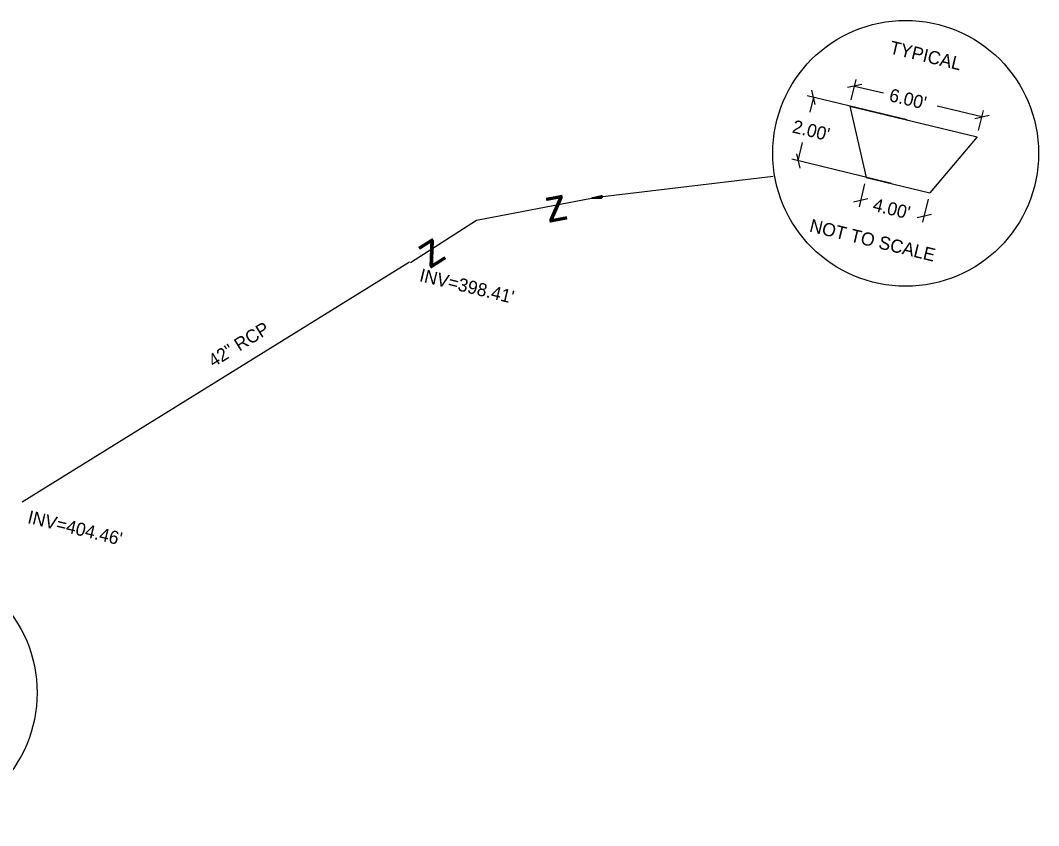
# Model space of a CAD drawing. Extents: x 1975859 to 1978323, y 778892 to 782836.
# Drawn here: x 1977755 to 1978066, y 779985 to 780231 of the extents above; entities that cross this region are included whole.
import ezdxf

# ---------------------------------------------------------------- set-up
doc = ezdxf.new("R2010")
doc.units = 0
for name, color, linetype in [('Exist Structure Minor Pipes RCP 42 Inch', 7, 'Continuous'), ('Exist Structure Minor Pipes RCP 42 Inch Invert', 7, 'Continuous'), ('Exist Structure Minor Pipes RCP 42 Inch Text', 7, 'Continuous'), ('Scratch_Level_8', 7, 'Continuous')]:
    doc.layers.add(name, color=color, linetype=linetype)

msp = doc.modelspace()

# ---------------------------------------------------------------- linework, layer by layer
at = {"layer": 'Exist Structure Minor Pipes RCP 42 Inch'}
msp.add_line((1977873.82, 780157.16), (1977755.54, 780083.84), dxfattribs=at)
at = {"layer": 'Scratch_Level_8'}
for p, q in [((1978008.8, 780206.78), (1978010.29, 780212.91)), ((1977997.74, 780205.34), (1977996.74, 780209.7)), ((1978012, 780211.46), (1978007.64, 780210.46)), ((1978009.82, 780210.96), (1978018.62, 780208.83)), ((1978025.82, 780200.59), (1977995.3, 780207.99)), ((1977997.24, 780207.52), (1977996.13, 780202.94)), ((1978008.33, 780204.83), (1978047.2, 780195.41)), ((1978008.33, 780204.83), (1978013.34, 780183.04)), ((1978048.69, 780201.53), (1978035.01, 780204.85)), ((1978047.68, 780197.35), (1978049.16, 780203.48)), ((1978046.51, 780201.03), (1978050.87, 780202.03)), ((1977992.53, 780188.09), (1977993.9, 780193.75)), ((1978047.2, 780195.41), (1978032.77, 780178.33)), ((1977992.03, 780190.27), (1977993.03, 780185.91)), ((1978021.11, 780181.15), (1977990.59, 780188.56)), ((1977984.93, 780183.31), (1977929.4, 780176.73)), ((1978012.86, 780181.1), (1978011.16, 780174.08)), ((1978013.34, 780183.04), (1978032.77, 780178.33)), ((1977932.38, 780177.08), (1977932.62, 780177.33)), ((1977932.38, 780177.08), (1977932.68, 780177.28)), ((1977932.38, 780177.08), (1977932.69, 780177.18)), ((1977932.68, 780176.9), (1977932.38, 780177.08)), ((1977932.38, 780177.08), (1977932.7, 780177.06)), ((1977932.38, 780177.08), (1977932.71, 780176.97)), ((1977932.66, 780177.38), (1977932.73, 780176.85)), ((1978013.81, 780176.52), (1978009.45, 780175.52)), ((1978032.3, 780176.38), (1978030.6, 780169.36)), ((1978028.89, 780170.81), (1978033.25, 780171.81))]:
    msp.add_line(p, q, dxfattribs=at)
for points in [[(1977874.1, 780157.02), (1977894.26, 780169.96), (1977929.4, 780176.73)], [(1977932.66, 780177.38), (1977932.42, 780177.45), (1977929.4, 780176.73), (1977932.51, 780176.74), (1977932.73, 780176.85)], [(1977932.62, 780176.8), (1977929.4, 780176.73), (1977932.54, 780177.42)], [(1977932.52, 780177.31), (1977929.4, 780176.73), (1977932.66, 780177.38), (1977932.62, 780177.33), (1977932.52, 780177.31), (1977932.38, 780177.08), (1977932.57, 780176.89), (1977932.68, 780176.9), (1977932.73, 780176.85), (1977929.4, 780176.73), (1977932.57, 780176.89)], [(1977929.58, 780176.74), (1977929.5, 780176.74), (1977929.59, 780176.76), (1977929.68, 780176.78), (1977929.59, 780176.75), (1977929.67, 780176.74), (1977929.76, 780176.75), (1977929.68, 780176.76), (1977929.77, 780176.8), (1977929.86, 780176.81), (1977929.77, 780176.77), (1977929.86, 780176.75), (1977929.95, 780176.76), (1977929.87, 780176.78), (1977929.95, 780176.83), (1977930.05, 780176.85), (1977929.96, 780176.8), (1977930.04, 780176.76), (1977930.14, 780176.77), (1977930.05, 780176.81), (1977930.14, 780176.87), (1977930.23, 780176.88), (1977930.15, 780176.82), (1977930.23, 780176.77), (1977930.32, 780176.78), (1977930.24, 780176.83), (1977930.32, 780176.9), (1977930.41, 780176.92), (1977930.33, 780176.84), (1977930.42, 780176.78), (1977930.51, 780176.79), (1977930.42, 780176.85), (1977930.51, 780176.93), (1977930.6, 780176.95), (1977930.52, 780176.86), (1977930.6, 780176.79), (1977930.7, 780176.8), (1977930.61, 780176.87), (1977930.69, 780176.97), (1977930.78, 780176.98), (1977930.7, 780176.88), (1977930.79, 780176.8), (1977930.88, 780176.81), (1977930.8, 780176.89), (1977930.87, 780177), (1977930.97, 780177.02), (1977930.89, 780176.91), (1977930.98, 780176.81), (1977931.07, 780176.82), (1977930.98, 780176.92), (1977931.06, 780177.04), (1977931.15, 780177.05), (1977931.08, 780176.93), (1977931.16, 780176.82), (1977931.26, 780176.83), (1977931.17, 780176.94), (1977931.24, 780177.07), (1977931.34, 780177.09), (1977931.26, 780176.95), (1977931.35, 780176.83), (1977931.45, 780176.83), (1977931.35, 780176.96), (1977931.43, 780177.1), (1977931.52, 780177.12), (1977931.45, 780176.97), (1977931.54, 780176.84), (1977931.63, 780176.84), (1977931.54, 780176.98), (1977931.61, 780177.14), (1977931.7, 780177.16), (1977931.63, 780177), (1977931.73, 780176.85), (1977931.82, 780176.85), (1977931.73, 780177), (1977931.8, 780177.17), (1977931.89, 780177.19), (1977931.82, 780177.02), (1977931.91, 780176.86), (1977932.01, 780176.86), (1977931.91, 780177.03), (1977931.98, 780177.21), (1977932.07, 780177.22), (1977932.01, 780177.04), (1977932.1, 780176.87), (1977932.19, 780176.87), (1977932.1, 780177.05), (1977932.16, 780177.24), (1977932.26, 780177.26), (1977932.19, 780177.06), (1977932.29, 780176.88), (1977932.38, 780176.88), (1977932.28, 780177.07), (1977932.35, 780177.28), (1977932.44, 780177.29), (1977932.38, 780177.08), (1977932.47, 780176.89)]]:
    msp.add_lwpolyline(points, dxfattribs=at)
for centre in [(1978025.41, 780190.4), (1977719.47, 780025.6)]:
    msp.add_circle(centre, 40.62, dxfattribs=at)

# ---------------------------------------------------------------- texts
at = {"layer": 'Exist Structure Minor Pipes RCP 42 Inch Invert'}
for s, p in [("INV=398.41'", (1977876.63, 780151.38)), ("INV=404.46'", (1977756.93, 780077.49))]:
    msp.add_text(s, height=4, rotation=346.3665, dxfattribs=at).set_placement(p)
at = {"layer": 'Exist Structure Minor Pipes RCP 42 Inch Text'}
msp.add_text('42" RCP', height=4, rotation=31.7967, dxfattribs=at).set_placement((1977813.94, 780124.87))
at = {"layer": 'Scratch_Level_8'}
for s, height, rotation, p in [('TYPICAL', 4, 346.3666, (1978020.24, 780220.96)), ("6.00'", 4, 346.3666, (1978020.09, 780206.41)), ("2.00'", 4, 346.3666, (1977990.53, 780196.8)), ('z', 10, 10.814, (1977916.16, 780169.1)), ("4.00'", 4, 346.3666, (1978015.11, 780172.89)), ('NOT TO SCALE', 4, 346.3666, (1977995.78, 780166.52)), ('z', 10, 32.5378, (1977879.97, 780154.88))]:
    msp.add_text(s, height=height, rotation=rotation, dxfattribs=at).set_placement(p)

doc.saveas('drawing.dxf')
